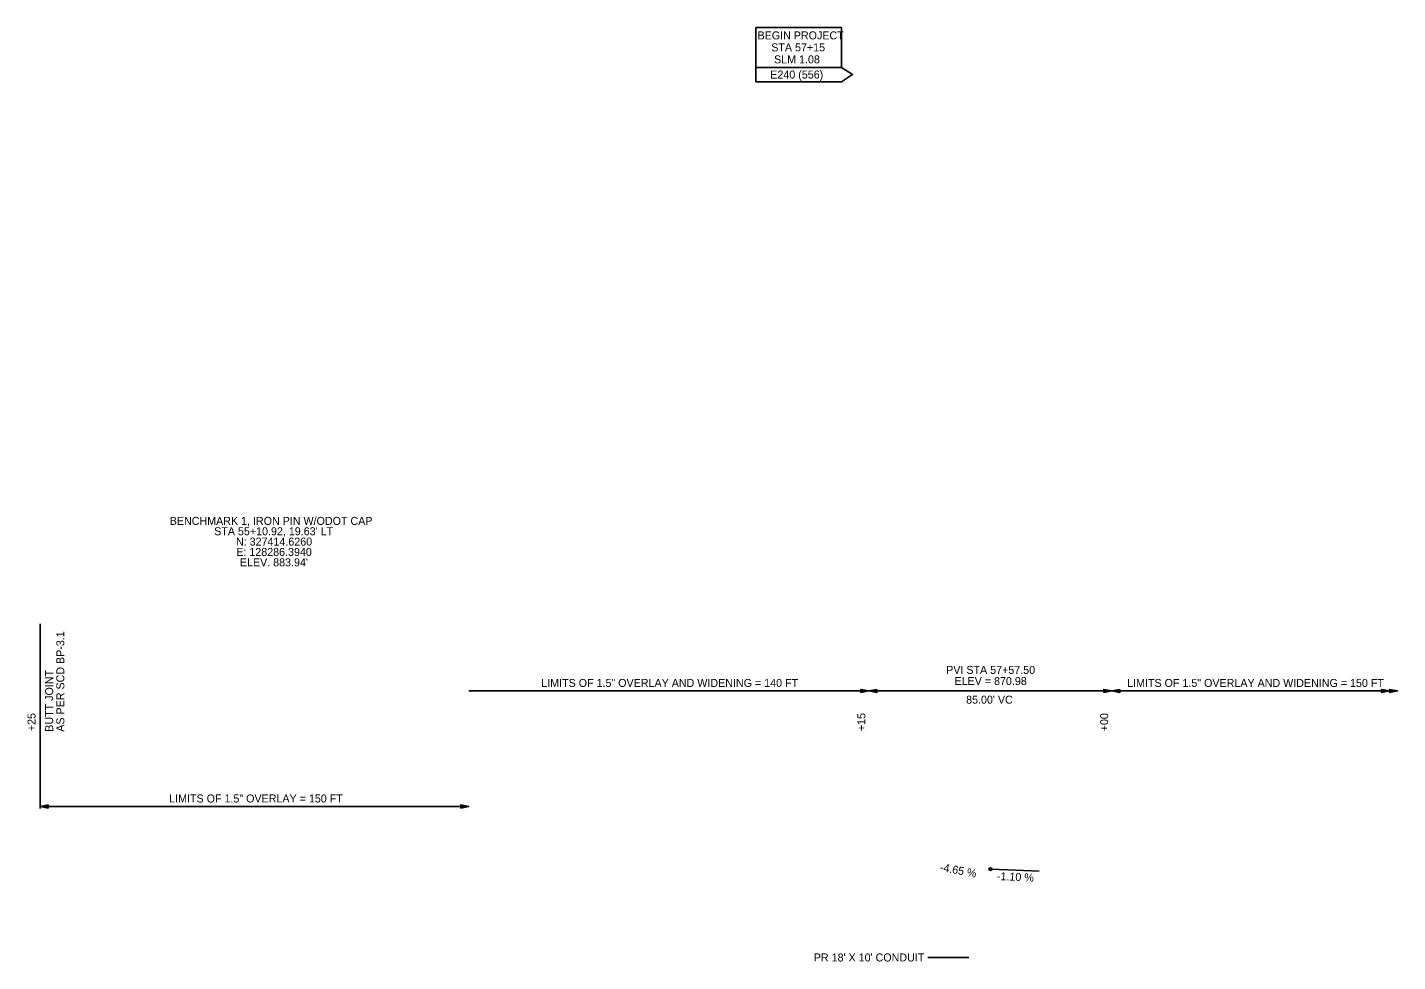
# Model space of a CAD drawing. Extents: x -593 to 958, y -48 to 786.
# Drawn here: x -593.3 to -113.8, y 459.4 to 786.4 of the extents above; entities that cross this region are included whole.
import ezdxf

# ---------------------------------------------------------------- set-up
doc = ezdxf.new("R2010")
doc.units = 0
doc.layers.add('PF_P_Grade_Line', color=7, linetype='Continuous')
doc.layers.add('PV_P_EOP', color=7, linetype='Continuous')

msp = doc.modelspace()

# ---------------------------------------------------------------- linework, layer by layer
at = {"layer": 'PF_P_Grade_Line'}
for p, q in [((-308.41, 786.4), (-338.41, 786.4)), ((-338.41, 767.4), (-338.41, 786.4)), ((-308.41, 772.4), (-308.41, 786.4)), ((-308.41, 772.4), (-338.41, 772.4)), ((-308.41, 767.4), (-338.41, 767.4)), ((-588.8, 512.97), (-588.8, 577.56)), ((-298.8, 554.12), (-438.8, 554.12)), ((-298.8, 554.12), (-213.8, 554.12)), ((-213.8, 554.12), (-113.8, 554.12)), ((-438.8, 513.68), (-588.8, 513.68)), ((-278.13, 460.82), (-263.8, 460.82))]:
    msp.add_line(p, q, dxfattribs=at)
for points in [[(-308.41, 772.4), (-304.53, 769.9), (-308.41, 767.4)], [(-256.3, 491.77), (-250.19, 491.5), (-239.26, 491.01)]]:
    msp.add_lwpolyline(points, dxfattribs=at)
msp.add_circle((-256.3, 491.77), 0.49, dxfattribs=at)
at = {"layer": 'PV_P_EOP'}
for points in [[(-301.6, 553.56), (-301.6, 554.68), (-298.8, 554.12)], [(-296, 554.68), (-296, 553.56), (-298.8, 554.12)], [(-216.6, 553.56), (-216.6, 554.68), (-213.8, 554.12)], [(-211, 554.68), (-211, 553.56), (-213.8, 554.12)], [(-119.4, 553.56), (-119.4, 554.68), (-116.6, 554.12)], [(-116.6, 553.56), (-116.6, 554.68), (-113.8, 554.12)], [(-586, 514.24), (-586, 513.12), (-588.8, 513.68)], [(-441.6, 513.12), (-441.6, 514.24), (-438.8, 513.68)]]:
    msp.add_lwpolyline(points, close=True, dxfattribs=at)

# ---------------------------------------------------------------- texts
at = {"layer": 'PF_P_Grade_Line'}
for s, p in [('BEGIN PROJECT', (-337.77, 782.2)), ('STA 57+15', (-332.97, 778)), ('SLM 1.08', (-331.98, 773.8)), ('E240 (556)', (-333.31, 768.5)), ('BENCHMARK 1, IRON PIN W/ODOT CAP', (-543.45, 612.25)), ("STA 55+10.92, 19.63' LT", (-527.9, 608.62)), ('N: 327414.6260', (-520.27, 605)), ('E: 128286.3940', (-520.16, 601.38)), ("ELEV. 883.94'", (-518.91, 597.75)), ('PVI STA 57+57.50', (-271.76, 560.09)), ('LIMITS OF 1.5" OVERLAY AND WIDENING = 140 FT', (-413.44, 555.52)), ('ELEV = 870.98', (-268.85, 556.19)), ('LIMITS OF 1.5" OVERLAY AND WIDENING = 150 FT', (-208.44, 555.52)), ("85.00' VC", (-264.78, 549.67)), ('LIMITS OF 1.5" OVERLAY = 150 FT', (-543.64, 515.08)), ("PR 18' X 10' CONDUIT", (-318.08, 459.42))]:
    msp.add_text(s, height=2.8, dxfattribs=at).set_placement(p)
for s, rotation, p in [('AS PER SCD BP-3.1', 90, (-580.34, 539.84)), ('BUTT JOINT', 90, (-584.24, 539.84)), ('+25', 90, (-590.41, 540.05)), ('+15', 90, (-300.05, 540.05)), ('+00', 90, (-215.08, 540.01)), ('-4.65 %', 349.4648, (-274.12, 491.14)), ('-1.10 %', 357.462, (-254.04, 487.94))]:
    msp.add_text(s, height=2.8, rotation=rotation, dxfattribs=at).set_placement(p)

doc.saveas('drawing.dxf')
